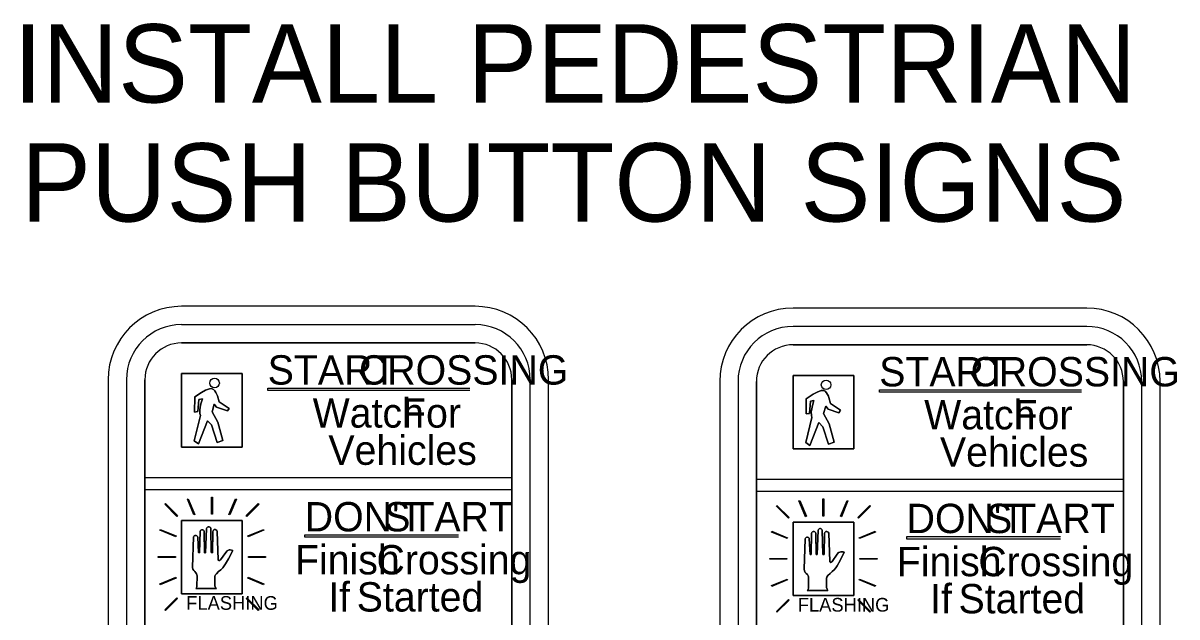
# Model space of a CAD drawing. Extents: x 0 to 3.01, y -0.05 to 1.83.
# Drawn here: x 1.2933 to 1.4408, y 1.6233 to 1.6992 of the extents above; entities that cross this region are included whole.
import ezdxf

# ---------------------------------------------------------------- set-up
doc = ezdxf.new("R2010")
doc.units = 0
doc.layers.add('TR_TS_Text', color=7, linetype='Continuous')

msp = doc.modelspace()

# ---------------------------------------------------------------- linework, layer by layer
at = {"layer": 'TR_TS_Text'}
for p, q in [((1.35109, 1.66063), (1.31356, 1.66063)), ((1.42926, 1.6604), (1.39173, 1.6604)), ((1.31356, 1.65829), (1.35109, 1.65829)), ((1.39173, 1.65806), (1.42926, 1.65806)), ((1.30652, 1.6536), (1.30652, 1.57854)), ((1.30887, 1.57854), (1.30887, 1.6536)), ((1.35578, 1.6536), (1.35578, 1.57854)), ((1.35813, 1.57854), (1.35813, 1.6536)), ((1.32461, 1.65253), (1.35042, 1.65253)), ((1.32461, 1.65222), (1.32461, 1.65253)), ((1.35042, 1.65222), (1.32461, 1.65222)), ((1.38469, 1.65337), (1.38469, 1.57831)), ((1.38704, 1.57831), (1.38704, 1.65337)), ((1.40278, 1.6523), (1.42859, 1.6523)), ((1.40278, 1.65199), (1.40278, 1.6523)), ((1.42859, 1.65199), (1.40278, 1.65199)), ((1.43395, 1.65337), (1.43395, 1.57831)), ((1.4363, 1.57831), (1.4363, 1.65337)), ((1.30887, 1.64109), (1.35578, 1.64109)), ((1.30887, 1.63952), (1.30887, 1.64109)), ((1.38704, 1.64086), (1.43395, 1.64086)), ((1.38704, 1.63929), (1.38704, 1.64086)), ((1.35578, 1.63952), (1.30887, 1.63952)), ((1.43395, 1.63929), (1.38704, 1.63929)), ((1.31744, 1.63561), (1.31356, 1.63561)), ((1.31356, 1.63561), (1.31356, 1.63092)), ((1.32132, 1.63561), (1.31744, 1.63561)), ((1.32132, 1.63092), (1.32132, 1.63561)), ((1.39561, 1.63538), (1.39173, 1.63538)), ((1.39173, 1.63538), (1.39173, 1.63069)), ((1.39949, 1.63538), (1.39561, 1.63538)), ((1.39949, 1.63069), (1.39949, 1.63538)), ((1.32931, 1.63377), (1.34898, 1.63377)), ((1.32931, 1.63345), (1.32931, 1.63377)), ((1.34898, 1.63345), (1.32931, 1.63345)), ((1.40625, 1.63354), (1.42591, 1.63354)), ((1.40625, 1.63322), (1.40625, 1.63354)), ((1.42591, 1.63322), (1.40625, 1.63322)), ((1.31356, 1.63092), (1.31356, 1.62623)), ((1.32132, 1.63092), (1.32132, 1.62623)), ((1.39173, 1.63069), (1.39173, 1.626)), ((1.39949, 1.63069), (1.39949, 1.626))]:
    msp.add_line(p, q, dxfattribs=at)
for points in [[(1.35109, 1.66298), (1.31356, 1.66298)], [(1.42926, 1.66275), (1.39173, 1.66275)], [(1.35109, 1.66063), (1.31356, 1.66063)], [(1.42926, 1.6604), (1.39173, 1.6604)], [(1.35109, 1.65829), (1.31356, 1.65829)], [(1.42926, 1.65806), (1.39173, 1.65806)], [(1.30418, 1.6536), (1.30418, 1.57854)], [(1.30652, 1.6536), (1.30652, 1.57854)], [(1.30887, 1.6536), (1.30887, 1.57854)], [(1.31356, 1.64499), (1.32132, 1.64499), (1.32132, 1.65438), (1.31356, 1.65438), (1.31356, 1.64499)], [(1.35578, 1.57854), (1.35578, 1.6536)], [(1.35813, 1.57854), (1.35813, 1.6536)], [(1.36047, 1.57854), (1.36047, 1.6536)], [(1.39173, 1.64476), (1.39949, 1.64476), (1.39949, 1.65415), (1.39173, 1.65415), (1.39173, 1.64476)], [(1.31597, 1.649), (1.31519, 1.64579), (1.31572, 1.64541), (1.31686, 1.64835), (1.31738, 1.64781), (1.3181, 1.64557), (1.31882, 1.64584), (1.31818, 1.64818), (1.31746, 1.64949), (1.31773, 1.65046), (1.31803, 1.65007), (1.31942, 1.64961), (1.31964, 1.64991), (1.31835, 1.65078), (1.31814, 1.65153), (1.31809, 1.6517), (1.31796, 1.65194), (1.31782, 1.65216), (1.31765, 1.65235), (1.31748, 1.65244), (1.31733, 1.65245), (1.31715, 1.65244), (1.31663, 1.65224), (1.31611, 1.65196), (1.31525, 1.6514), (1.31523, 1.64945), (1.31565, 1.64952), (1.31578, 1.65106), (1.31623, 1.65116), (1.31603, 1.65053), (1.31594, 1.6501), (1.31589, 1.6497), (1.31591, 1.64926), (1.31597, 1.649)], [(1.31591, 1.64926), (1.31589, 1.6497), (1.31594, 1.6501), (1.31603, 1.65053), (1.31623, 1.65116), (1.31578, 1.65106), (1.31565, 1.64952), (1.31523, 1.64945), (1.31525, 1.6514), (1.31611, 1.65196), (1.31663, 1.65224), (1.31715, 1.65244), (1.31733, 1.65245), (1.31748, 1.65244), (1.31765, 1.65235), (1.31782, 1.65216), (1.31796, 1.65194), (1.31809, 1.6517), (1.31814, 1.65153), (1.31835, 1.65078), (1.31964, 1.64991), (1.31942, 1.64961), (1.31803, 1.65007), (1.31773, 1.65046), (1.31746, 1.64949), (1.31818, 1.64818), (1.31882, 1.64584), (1.3181, 1.64557), (1.31738, 1.64781), (1.31686, 1.64835), (1.31572, 1.64541), (1.31519, 1.64579), (1.31597, 1.649), (1.31591, 1.64926)], [(1.38235, 1.65337), (1.38235, 1.57831)], [(1.38469, 1.65337), (1.38469, 1.57831)], [(1.38704, 1.65337), (1.38704, 1.57831)], [(1.39414, 1.64877), (1.39336, 1.64556), (1.39389, 1.64518), (1.39503, 1.64812), (1.39555, 1.64758), (1.39627, 1.64534), (1.39699, 1.64561), (1.39635, 1.64796), (1.39563, 1.64926), (1.3959, 1.65023), (1.3962, 1.64984), (1.39759, 1.64938), (1.39781, 1.64968), (1.39652, 1.65055), (1.39631, 1.6513), (1.39626, 1.65147), (1.39613, 1.65171), (1.39599, 1.65193), (1.39582, 1.65212), (1.39565, 1.65221), (1.3955, 1.65222), (1.39532, 1.65221), (1.3948, 1.65201), (1.39428, 1.65173), (1.39342, 1.65117), (1.3934, 1.64922), (1.39382, 1.64929), (1.39395, 1.65083), (1.3944, 1.65093), (1.3942, 1.6503), (1.39411, 1.64987), (1.39406, 1.64947), (1.39408, 1.64903), (1.39414, 1.64877)], [(1.39408, 1.64903), (1.39406, 1.64947), (1.39411, 1.64987), (1.3942, 1.6503), (1.3944, 1.65093), (1.39395, 1.65083), (1.39382, 1.64929), (1.3934, 1.64922), (1.39342, 1.65117), (1.39428, 1.65173), (1.3948, 1.65201), (1.39532, 1.65221), (1.3955, 1.65222), (1.39565, 1.65221), (1.39582, 1.65212), (1.39599, 1.65193), (1.39613, 1.65171), (1.39626, 1.65147), (1.39631, 1.6513), (1.39652, 1.65055), (1.39781, 1.64968), (1.39759, 1.64938), (1.3962, 1.64984), (1.3959, 1.65023), (1.39563, 1.64926), (1.39635, 1.64796), (1.39699, 1.64561), (1.39627, 1.64534), (1.39555, 1.64758), (1.39503, 1.64812), (1.39389, 1.64518), (1.39336, 1.64556), (1.39414, 1.64877), (1.39408, 1.64903)], [(1.43395, 1.57831), (1.43395, 1.65337)], [(1.4363, 1.57831), (1.4363, 1.65337)], [(1.43864, 1.57831), (1.43864, 1.65337)], [(1.31356, 1.62623), (1.32132, 1.62623), (1.32132, 1.63561), (1.31356, 1.63561), (1.31356, 1.62623)], [(1.31538, 1.62688), (1.31802, 1.62688), (1.31791, 1.62703), (1.31783, 1.62724), (1.31782, 1.62845), (1.31787, 1.62859), (1.31801, 1.62879), (1.31828, 1.62906), (1.31856, 1.6293), (1.31883, 1.62953), (1.31901, 1.62978), (1.31919, 1.63004), (1.31957, 1.63071), (1.3201, 1.63176), (1.31995, 1.6318), (1.31979, 1.63183), (1.31966, 1.63183), (1.31954, 1.63179), (1.31938, 1.63171), (1.31921, 1.63152), (1.31855, 1.63057), (1.31844, 1.63048), (1.3184, 1.63046), (1.31834, 1.63046), (1.31826, 1.63052), (1.31824, 1.63055), (1.31811, 1.6342), (1.31805, 1.63431), (1.31796, 1.63438), (1.31789, 1.63442), (1.31775, 1.63442), (1.31766, 1.63435), (1.3176, 1.63429), (1.31756, 1.6342), (1.31753, 1.63147), (1.31735, 1.63148), (1.31729, 1.63458), (1.31724, 1.63468), (1.31716, 1.63474), (1.31708, 1.63478), (1.31697, 1.63478), (1.31688, 1.63474), (1.3168, 1.63467), (1.31676, 1.63458), (1.31664, 1.63147), (1.31651, 1.63147), (1.31647, 1.63421), (1.31642, 1.6343), (1.31635, 1.63437), (1.31626, 1.63441), (1.31611, 1.63441), (1.31604, 1.63437), (1.31597, 1.6343), (1.31593, 1.63422), (1.31586, 1.63147), (1.31572, 1.63148), (1.31563, 1.63348), (1.3156, 1.63356), (1.31553, 1.63363), (1.31541, 1.63368), (1.31531, 1.63368), (1.31524, 1.63366), (1.31519, 1.63362), (1.31513, 1.63356), (1.31509, 1.63349), (1.31498, 1.6296), (1.31501, 1.62938), (1.31511, 1.62919), (1.31524, 1.62906), (1.31539, 1.62892), (1.31549, 1.62876), (1.31552, 1.62863), (1.31555, 1.62852), (1.31553, 1.62715), (1.31547, 1.62698), (1.31538, 1.62688)], [(1.31547, 1.62698), (1.31553, 1.62715), (1.31555, 1.62852), (1.31552, 1.62863), (1.31549, 1.62876), (1.31539, 1.62892), (1.31524, 1.62906), (1.31511, 1.62919), (1.31501, 1.62938), (1.31498, 1.6296), (1.31509, 1.63349), (1.31513, 1.63356), (1.31519, 1.63362), (1.31524, 1.63366), (1.31531, 1.63368), (1.31541, 1.63368), (1.31553, 1.63363), (1.3156, 1.63356), (1.31563, 1.63348), (1.31572, 1.63148), (1.31586, 1.63147), (1.31593, 1.63422), (1.31597, 1.6343), (1.31604, 1.63437), (1.31611, 1.63441), (1.31626, 1.63441), (1.31635, 1.63437), (1.31642, 1.6343), (1.31647, 1.63421), (1.31651, 1.63147), (1.31664, 1.63147), (1.31676, 1.63458), (1.3168, 1.63467), (1.31688, 1.63474), (1.31697, 1.63478), (1.31708, 1.63478), (1.31716, 1.63474), (1.31724, 1.63468), (1.31729, 1.63458), (1.31735, 1.63148), (1.31753, 1.63147), (1.31756, 1.6342), (1.3176, 1.63429), (1.31766, 1.63435), (1.31775, 1.63442), (1.31789, 1.63442), (1.31796, 1.63438), (1.31805, 1.63431), (1.31811, 1.6342), (1.31824, 1.63055), (1.31826, 1.63052), (1.31834, 1.63046), (1.3184, 1.63046), (1.31844, 1.63048), (1.31855, 1.63057), (1.31921, 1.63152), (1.31938, 1.63171), (1.31954, 1.63179), (1.31966, 1.63183), (1.31979, 1.63183), (1.31995, 1.6318), (1.3201, 1.63176), (1.31957, 1.63071), (1.31919, 1.63004), (1.31901, 1.62978), (1.31883, 1.62953), (1.31856, 1.6293), (1.31828, 1.62906), (1.31801, 1.62879), (1.31787, 1.62859), (1.31782, 1.62845), (1.31783, 1.62724), (1.31791, 1.62703), (1.31802, 1.62688), (1.31538, 1.62688), (1.31547, 1.62698)], [(1.39173, 1.626), (1.39949, 1.626), (1.39949, 1.63538), (1.39173, 1.63538), (1.39173, 1.626)], [(1.39355, 1.62665), (1.39619, 1.62665), (1.39608, 1.6268), (1.396, 1.62701), (1.39599, 1.62822), (1.39604, 1.62836), (1.39618, 1.62856), (1.39645, 1.62883), (1.39673, 1.62907), (1.397, 1.6293), (1.39718, 1.62955), (1.39736, 1.62981), (1.39774, 1.63048), (1.39827, 1.63153), (1.39812, 1.63157), (1.39796, 1.6316), (1.39783, 1.6316), (1.39771, 1.63156), (1.39755, 1.63148), (1.39738, 1.63129), (1.39672, 1.63034), (1.39661, 1.63025), (1.39657, 1.63023), (1.39651, 1.63023), (1.39643, 1.63029), (1.39641, 1.63033), (1.39628, 1.63397), (1.39622, 1.63409), (1.39613, 1.63415), (1.39606, 1.63419), (1.39592, 1.63419), (1.39583, 1.63412), (1.39577, 1.63406), (1.39573, 1.63397), (1.3957, 1.63124), (1.39552, 1.63125), (1.39546, 1.63435), (1.39541, 1.63445), (1.39533, 1.63451), (1.39525, 1.63455), (1.39514, 1.63455), (1.39505, 1.63451), (1.39497, 1.63444), (1.39493, 1.63435), (1.39481, 1.63124), (1.39468, 1.63125), (1.39464, 1.63398), (1.39459, 1.63407), (1.39452, 1.63414), (1.39443, 1.63418), (1.39428, 1.63418), (1.39421, 1.63414), (1.39414, 1.63407), (1.3941, 1.63399), (1.39403, 1.63124), (1.3939, 1.63125), (1.3938, 1.63325), (1.39377, 1.63333), (1.3937, 1.63341), (1.39358, 1.63345), (1.39348, 1.63345), (1.39341, 1.63343), (1.39336, 1.63339), (1.3933, 1.63333), (1.39326, 1.63326), (1.39315, 1.62937), (1.39318, 1.62916), (1.39328, 1.62896), (1.39341, 1.62883), (1.39356, 1.62869), (1.39366, 1.62853), (1.39369, 1.6284), (1.39372, 1.62829), (1.3937, 1.62692), (1.39364, 1.62676), (1.39355, 1.62665)], [(1.39364, 1.62676), (1.3937, 1.62692), (1.39372, 1.62829), (1.39369, 1.6284), (1.39366, 1.62853), (1.39356, 1.62869), (1.39341, 1.62883), (1.39328, 1.62896), (1.39318, 1.62916), (1.39315, 1.62937), (1.39326, 1.63326), (1.3933, 1.63333), (1.39336, 1.63339), (1.39341, 1.63343), (1.39348, 1.63345), (1.39358, 1.63345), (1.3937, 1.63341), (1.39377, 1.63333), (1.3938, 1.63325), (1.3939, 1.63125), (1.39403, 1.63124), (1.3941, 1.63399), (1.39414, 1.63407), (1.39421, 1.63414), (1.39428, 1.63418), (1.39443, 1.63418), (1.39452, 1.63414), (1.39459, 1.63407), (1.39464, 1.63398), (1.39468, 1.63125), (1.39481, 1.63124), (1.39493, 1.63435), (1.39497, 1.63444), (1.39505, 1.63451), (1.39514, 1.63455), (1.39525, 1.63455), (1.39533, 1.63451), (1.39541, 1.63445), (1.39546, 1.63435), (1.39552, 1.63125), (1.3957, 1.63124), (1.39573, 1.63397), (1.39577, 1.63406), (1.39583, 1.63412), (1.39592, 1.63419), (1.39606, 1.63419), (1.39613, 1.63415), (1.39622, 1.63409), (1.39628, 1.63397), (1.39641, 1.63033), (1.39643, 1.63029), (1.39651, 1.63023), (1.39657, 1.63023), (1.39661, 1.63025), (1.39672, 1.63034), (1.39738, 1.63129), (1.39755, 1.63148), (1.39771, 1.63156), (1.39783, 1.6316), (1.39796, 1.6316), (1.39812, 1.63157), (1.39827, 1.63153), (1.39774, 1.63048), (1.39736, 1.62981), (1.39718, 1.62955), (1.397, 1.6293), (1.39673, 1.62907), (1.39645, 1.62883), (1.39618, 1.62856), (1.39604, 1.62836), (1.39599, 1.62822), (1.396, 1.62701), (1.39608, 1.6268), (1.39619, 1.62665), (1.39355, 1.62665), (1.39364, 1.62676)]]:
    msp.add_lwpolyline(points, dxfattribs=at)
for points in [[(1.31356, 1.65438), (1.32132, 1.65438), (1.32132, 1.64499), (1.31356, 1.64499)], [(1.39173, 1.65415), (1.39949, 1.65415), (1.39949, 1.64476), (1.39173, 1.64476)], [(1.31296, 1.63612), (1.31142, 1.63767), (1.3115, 1.63776), (1.31305, 1.63621)], [(1.31514, 1.63631), (1.3143, 1.63833), (1.31442, 1.63838), (1.31526, 1.63636)], [(1.31738, 1.63639), (1.31738, 1.63858), (1.3175, 1.63858), (1.3175, 1.63639)], [(1.31962, 1.63636), (1.32046, 1.63838), (1.32057, 1.63833), (1.31973, 1.63631)], [(1.32183, 1.63621), (1.32337, 1.63776), (1.32346, 1.63767), (1.32191, 1.63612)], [(1.39113, 1.63589), (1.38959, 1.63744), (1.38967, 1.63753), (1.39122, 1.63598)], [(1.39331, 1.63608), (1.39248, 1.6381), (1.39259, 1.63815), (1.39343, 1.63613)], [(1.39555, 1.63616), (1.39555, 1.63835), (1.39567, 1.63835), (1.39567, 1.63616)], [(1.39779, 1.63613), (1.39863, 1.63815), (1.39874, 1.6381), (1.3979, 1.63608)], [(1.4, 1.63598), (1.40154, 1.63753), (1.40163, 1.63744), (1.40008, 1.63589)], [(1.31281, 1.63351), (1.31079, 1.63435), (1.31084, 1.63446), (1.31286, 1.63362)], [(1.31356, 1.63561), (1.32132, 1.63561), (1.32132, 1.62623), (1.31356, 1.62623)], [(1.32202, 1.63362), (1.32404, 1.63446), (1.32409, 1.63435), (1.32206, 1.63351)], [(1.39098, 1.63328), (1.38896, 1.63412), (1.38901, 1.63423), (1.39103, 1.63339)], [(1.39173, 1.63538), (1.39949, 1.63538), (1.39949, 1.626), (1.39173, 1.626)], [(1.40019, 1.63339), (1.40221, 1.63423), (1.40226, 1.63412), (1.40023, 1.63328)], [(1.31278, 1.63086), (1.31059, 1.63086), (1.31059, 1.63098), (1.31278, 1.63098)], [(1.3221, 1.63098), (1.32429, 1.63098), (1.32429, 1.63086), (1.3221, 1.63086)], [(1.39095, 1.63063), (1.38876, 1.63063), (1.38876, 1.63075), (1.39095, 1.63075)], [(1.40027, 1.63075), (1.40246, 1.63075), (1.40246, 1.63063), (1.40027, 1.63063)], [(1.31286, 1.62822), (1.31084, 1.62738), (1.31079, 1.6275), (1.31281, 1.62833)], [(1.32206, 1.62833), (1.32409, 1.6275), (1.32404, 1.62738), (1.32202, 1.62822)], [(1.39103, 1.62799), (1.38901, 1.62715), (1.38896, 1.62727), (1.39098, 1.6281)], [(1.40023, 1.6281), (1.40226, 1.62727), (1.40221, 1.62715), (1.40019, 1.62799)], [(1.31296, 1.62572), (1.31142, 1.62417), (1.3115, 1.62408), (1.31305, 1.62563)], [(1.32191, 1.62572), (1.32346, 1.62417), (1.32337, 1.62408), (1.32183, 1.62563)], [(1.39113, 1.62549), (1.38959, 1.62394), (1.38967, 1.62385), (1.39122, 1.6254)], [(1.40008, 1.62549), (1.40163, 1.62394), (1.40154, 1.62385), (1.4, 1.6254)]]:
    msp.add_lwpolyline(points, close=True, dxfattribs=at)
for centre in [(1.31778, 1.65317), (1.31778, 1.65317), (1.39595, 1.65294), (1.39595, 1.65294)]:
    msp.add_circle(centre, 0.000614, dxfattribs=at)
for centre, radius, start, end in [((1.31356, 1.6536), 0.00938, 90, 180), ((1.35109, 1.6536), 0.00938, 360, 90), ((1.39173, 1.65337), 0.00938, 90, 180), ((1.42926, 1.65337), 0.00938, 360, 90), ((1.31356, 1.6536), 0.00704, 90, 180), ((1.31356, 1.6536), 0.00704, 90, 180), ((1.35109, 1.6536), 0.00704, 360, 90), ((1.35109, 1.6536), 0.00704, 360, 90), ((1.39173, 1.65337), 0.00704, 90, 180), ((1.39173, 1.65337), 0.00704, 90, 180), ((1.42926, 1.65337), 0.00704, 360, 90), ((1.42926, 1.65337), 0.00704, 360, 90), ((1.31356, 1.6536), 0.00469, 90, 180), ((1.31356, 1.6536), 0.00469, 90, 180), ((1.35109, 1.6536), 0.00469, 360, 90), ((1.35109, 1.6536), 0.00469, 360, 90), ((1.39173, 1.65337), 0.00469, 90, 180), ((1.39173, 1.65337), 0.00469, 90, 180), ((1.42926, 1.65337), 0.00469, 360, 90), ((1.42926, 1.65337), 0.00469, 360, 90)]:
    msp.add_arc(centre, radius, start, end, dxfattribs=at)

# ---------------------------------------------------------------- texts
for s, height, p in [('INSTALL PEDESTRIAN', 0.010008, (1.29207, 1.68904)), ('PUSH BUTTON SIGNS', 0.010008, (1.29305, 1.67382)), ('START', 0.003753, (1.32457, 1.65297)), ('CROSSING', 0.003753, (1.33623, 1.65297)), ('START', 0.003753, (1.40274, 1.65274)), ('CROSSING', 0.003753, (1.4144, 1.65274)), ('Watch', 0.003753, (1.33032, 1.64747)), ('For', 0.003753, (1.34175, 1.64747)), ('Watch', 0.003753, (1.40849, 1.64724)), ('For', 0.003753, (1.41992, 1.64724)), ('Vehicles', 0.003753, (1.33233, 1.64271)), ('Vehicles', 0.003753, (1.4105, 1.64248)), ("DON'T", 0.003753, (1.32931, 1.6342)), ('START', 0.003753, (1.33947, 1.6342)), ("DON'T", 0.003753, (1.40624, 1.63398)), ('START', 0.003753, (1.4164, 1.63398)), ('Finish', 0.003753, (1.32806, 1.6287)), ('Crossing', 0.003753, (1.33848, 1.6287)), ('Finish', 0.003753, (1.40499, 1.62847)), ('Crossing', 0.003753, (1.41541, 1.62847)), ('If', 0.003753, (1.33231, 1.62395)), ('Started', 0.003753, (1.33595, 1.62395)), ('If', 0.003753, (1.40924, 1.62372)), ('Started', 0.003753, (1.41288, 1.62372)), ('FLASHING', 0.001751, (1.31416, 1.62417)), ('FLASHING', 0.001751, (1.39233, 1.62394))]:
    msp.add_text(s, height=height, rotation=360, dxfattribs=at).set_placement(p)

doc.saveas('drawing.dxf')
